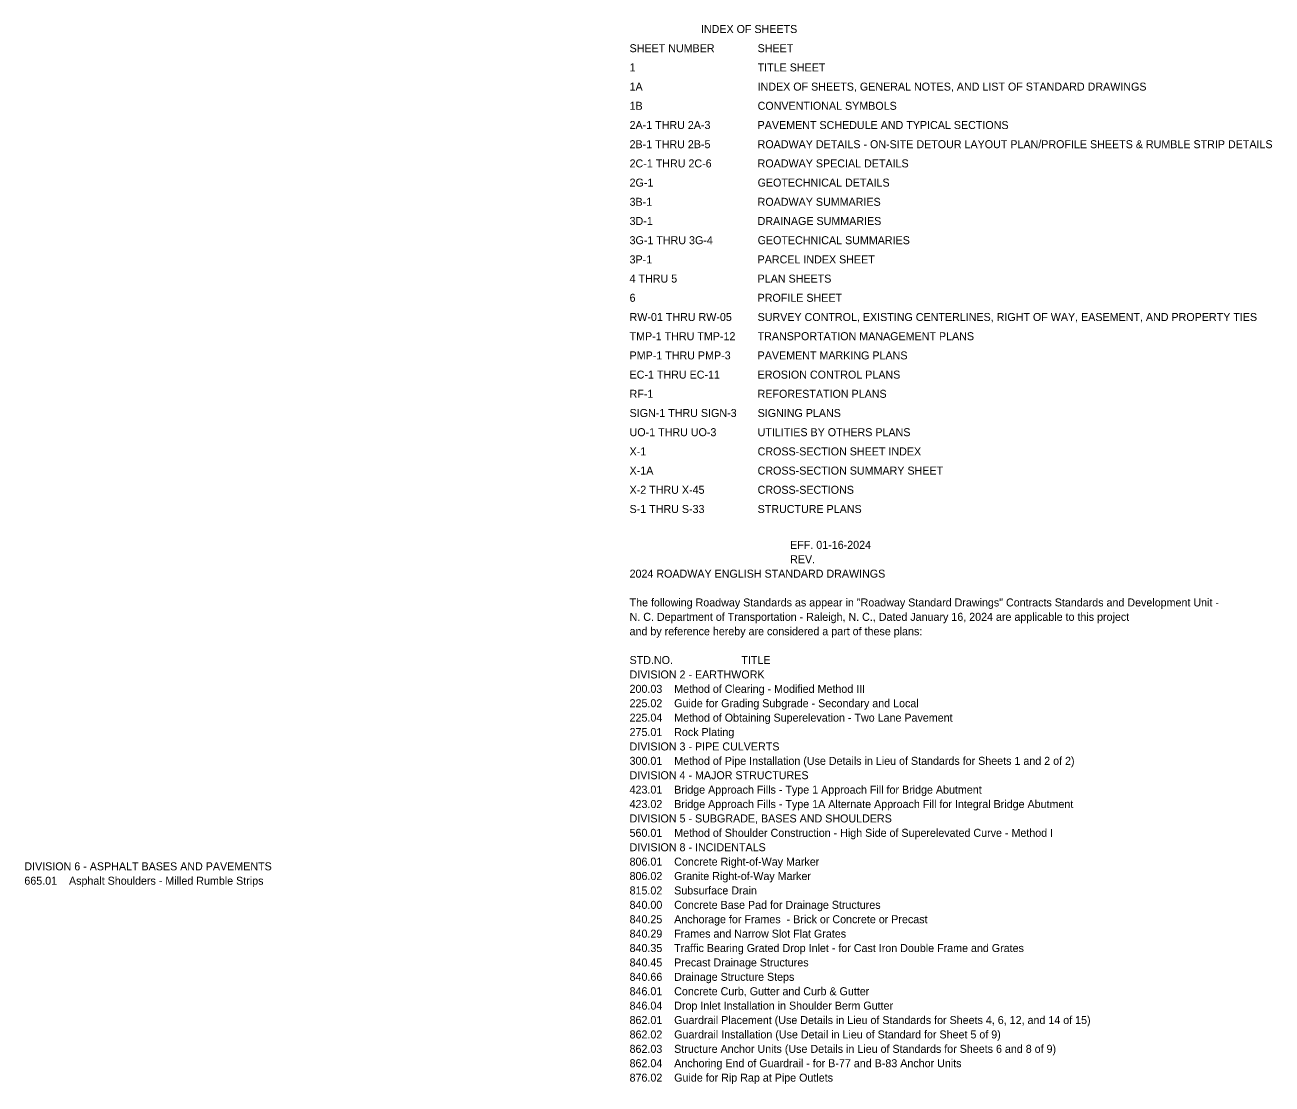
# Model space of a CAD drawing. Extents: x 2030341 to 2032444, y 1407825 to 1408818.
# Drawn here: x 2030341 to 2031510, y 1407825 to 1408818 of the extents above; entities that cross this region are included whole.
import ezdxf

# ---------------------------------------------------------------- set-up
doc = ezdxf.new("R2010")
doc.units = 0
doc.layers.add('Sheet_Data_Text_CELL', color=7, linetype='Continuous')

msp = doc.modelspace()

# ---------------------------------------------------------------- texts
at = {"layer": 'Sheet_Data_Text_CELL'}
for s, p in [('                        INDEX OF SHEETS ', (2030907.4, 1408810.5)), ('SHEET NUMBER', (2030907.4, 1408792.5)), ('SHEET   ', (2031027.4, 1408792.5)), ('1                       ', (2030907.4, 1408774.5)), ('TITLE SHEET', (2031027.4, 1408774.5)), ('1A                      ', (2030907.4, 1408756.5)), ('INDEX OF SHEETS, GENERAL NOTES, AND LIST OF STANDARD DRAWINGS', (2031027.4, 1408756.5)), ('1B                      ', (2030907.4, 1408738.5)), ('CONVENTIONAL SYMBOLS', (2031027.4, 1408738.5)), ('2A-1 THRU 2A-3           ', (2030907.4, 1408720.5)), ('PAVEMENT SCHEDULE AND TYPICAL SECTIONS', (2031027.4, 1408720.5)), ('2B-1 THRU 2B-5           ', (2030907.4, 1408702.5)), ('ROADWAY DETAILS - ON-SITE DETOUR LAYOUT PLAN/PROFILE SHEETS & RUMBLE STRIP DETAILS', (2031027.4, 1408702.5)), ('2C-1 THRU 2C-6           ', (2030907.4, 1408684.5)), ('ROADWAY SPECIAL DETAILS', (2031027.4, 1408684.5)), ('2G-1', (2030907.4, 1408666.5)), ('GEOTECHNICAL DETAILS', (2031027.4, 1408666.5)), ('3B-1           ', (2030907.4, 1408648.5)), ('ROADWAY SUMMARIES', (2031027.4, 1408648.5)), ('3D-1           ', (2030907.4, 1408630.5)), ('DRAINAGE SUMMARIES', (2031027.4, 1408630.5)), ('3G-1 THRU 3G-4          ', (2030907.4, 1408612.5)), ('GEOTECHNICAL SUMMARIES', (2031027.4, 1408612.5)), ('3P-1', (2030907.4, 1408594.5)), ('PARCEL INDEX SHEET', (2031027.4, 1408594.5)), ('4 THRU 5                  ', (2030907.4, 1408576.5)), ('PLAN SHEETS', (2031027.4, 1408576.5)), ('6', (2030907.4, 1408558.5)), ('PROFILE SHEET', (2031027.4, 1408558.5)), ('RW-01 THRU RW-05      ', (2030907.4, 1408540.5)), ('SURVEY CONTROL, EXISTING CENTERLINES, RIGHT OF WAY, EASEMENT, AND PROPERTY TIES', (2031027.4, 1408540.5)), ('TMP-1 THRU TMP-12     ', (2030907.4, 1408522.5)), ('TRANSPORTATION MANAGEMENT PLANS', (2031027.4, 1408522.5)), ('PMP-1 THRU PMP-3      ', (2030907.4, 1408504.5)), ('PAVEMENT MARKING PLANS', (2031027.4, 1408504.5)), ('EC-1 THRU EC-11      ', (2030907.4, 1408486.5)), ('EROSION CONTROL PLANS', (2031027.4, 1408486.5)), ('RF-1', (2030907.4, 1408468.5)), ('REFORESTATION PLANS', (2031027.4, 1408468.5)), ('SIGN-1 THRU SIGN-3     ', (2030907.4, 1408450.5)), ('SIGNING PLANS', (2031027.4, 1408450.5)), ('UO-1 THRU UO-3     ', (2030907.4, 1408432.5)), ('UTILITIES BY OTHERS PLANS', (2031027.4, 1408432.5)), ('X-1', (2030907.4, 1408414.5)), ('CROSS-SECTION SHEET INDEX', (2031027.4, 1408414.5)), ('X-1A', (2030907.4, 1408396.5)), ('CROSS-SECTION SUMMARY SHEET', (2031027.4, 1408396.5)), ('X-2 THRU X-45             ', (2030907.4, 1408378.5)), ('CROSS-SECTIONS        ', (2031027.4, 1408378.5)), ('S-1 THRU S-33             ', (2030907.4, 1408360.5)), ('STRUCTURE PLANS', (2031027.4, 1408360.5)), ('                                                      EFF. 01-16-2024', (2030907.4, 1408326.9)), ('                                                      REV. ', (2030907.4, 1408313.4)), ('2024 ROADWAY ENGLISH STANDARD DRAWINGS', (2030907.4, 1408299.9)), ('The following Roadway Standards as appear in "Roadway Standard Drawings" Contracts Standards and Development Unit -', (2030907.4, 1408272.9)), ('N. C. Department of Transportation - Raleigh, N. C., Dated January 16, 2024 are applicable to this project', (2030907.4, 1408259.4)), ('and by reference hereby are considered a part of these plans:', (2030907.4, 1408245.9)), ('STD.NO.                       TITLE', (2030907.4, 1408218.9)), ('DIVISION 2 - EARTHWORK', (2030907.4, 1408205.4)), ('200.03    Method of Clearing - Modified Method III', (2030907.4, 1408191.9)), ('225.02    Guide for Grading Subgrade - Secondary and Local', (2030907.4, 1408178.4)), ('225.04    Method of Obtaining Superelevation - Two Lane Pavement', (2030907.4, 1408164.9)), ('275.01    Rock Plating ', (2030907.4, 1408151.4)), ('DIVISION 3 - PIPE CULVERTS', (2030907.4, 1408137.9)), ('300.01    Method of Pipe Installation (Use Details in Lieu of Standards for Sheets 1 and 2 of 2)', (2030907.4, 1408124.4)), ('DIVISION 4 - MAJOR STRUCTURES', (2030907.4, 1408110.9)), ('423.01    Bridge Approach Fills - Type 1 Approach Fill for Bridge Abutment', (2030907.4, 1408097.4)), ('423.02    Bridge Approach Fills - Type 1A Alternate Approach Fill for Integral Bridge Abutment', (2030907.4, 1408083.9)), ('DIVISION 5 - SUBGRADE, BASES AND SHOULDERS', (2030907.4, 1408070.4)), ('560.01    Method of Shoulder Construction - High Side of Superelevated Curve - Method I', (2030907.4, 1408056.9)), ('DIVISION 8 - INCIDENTALS', (2030907.4, 1408043.4)), ('DIVISION 6 - ASPHALT BASES AND PAVEMENTS', (2030340.2, 1408025.5)), ('806.01    Concrete Right-of-Way Marker', (2030907.4, 1408029.9)), ('665.01    Asphalt Shoulders - Milled Rumble Strips', (2030340.2, 1408012)), ('806.02    Granite Right-of-Way Marker', (2030907.4, 1408016.4)), ('815.02    Subsurface Drain', (2030907.4, 1408002.9)), ('840.00    Concrete Base Pad for Drainage Structures', (2030907.4, 1407989.4)), ('840.25    Anchorage for Frames  - Brick or Concrete or Precast', (2030907.4, 1407975.9)), ('840.29    Frames and Narrow Slot Flat Grates', (2030907.4, 1407962.4)), ('840.35    Traffic Bearing Grated Drop Inlet - for Cast Iron Double Frame and Grates', (2030907.4, 1407948.9)), ('840.45    Precast Drainage Structures', (2030907.4, 1407935.4)), ('840.66    Drainage Structure Steps', (2030907.4, 1407921.9)), ('846.01    Concrete Curb, Gutter and Curb & Gutter', (2030907.4, 1407908.4)), ('846.04    Drop Inlet Installation in Shoulder Berm Gutter', (2030907.4, 1407894.9)), ('862.01    Guardrail Placement (Use Details in Lieu of Standards for Sheets 4, 6, 12, and 14 of 15)', (2030907.4, 1407881.4)), ('862.02    Guardrail Installation (Use Detail in Lieu of Standard for Sheet 5 of 9)', (2030907.4, 1407867.9)), ('862.03    Structure Anchor Units (Use Details in Lieu of Standards for Sheets 6 and 8 of 9)', (2030907.4, 1407854.4)), ('862.04    Anchoring End of Guardrail - for B-77 and B-83 Anchor Units', (2030907.4, 1407840.9)), ('876.02    Guide for Rip Rap at Pipe Outlets', (2030907.4, 1407827.4))]:
    msp.add_text(s, height=7.5, dxfattribs=at).set_placement(p)

doc.saveas('drawing.dxf')
